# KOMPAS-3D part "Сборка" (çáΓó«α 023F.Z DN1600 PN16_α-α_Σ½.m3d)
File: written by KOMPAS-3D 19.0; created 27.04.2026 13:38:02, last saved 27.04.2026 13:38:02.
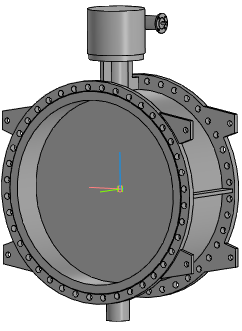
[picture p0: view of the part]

Document properties: Автор: Энергия; Полное имя файла: ..\..\Затвор 023F.Z DN200-DN1600_редуктор с входным фланцем\Затвор 023F.Z DN1600 PN16 + редуктор с входным фланцем.a3d

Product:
- Part/product: Сборка
    Масса: 4449.02

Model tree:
1. Операция без истории:1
